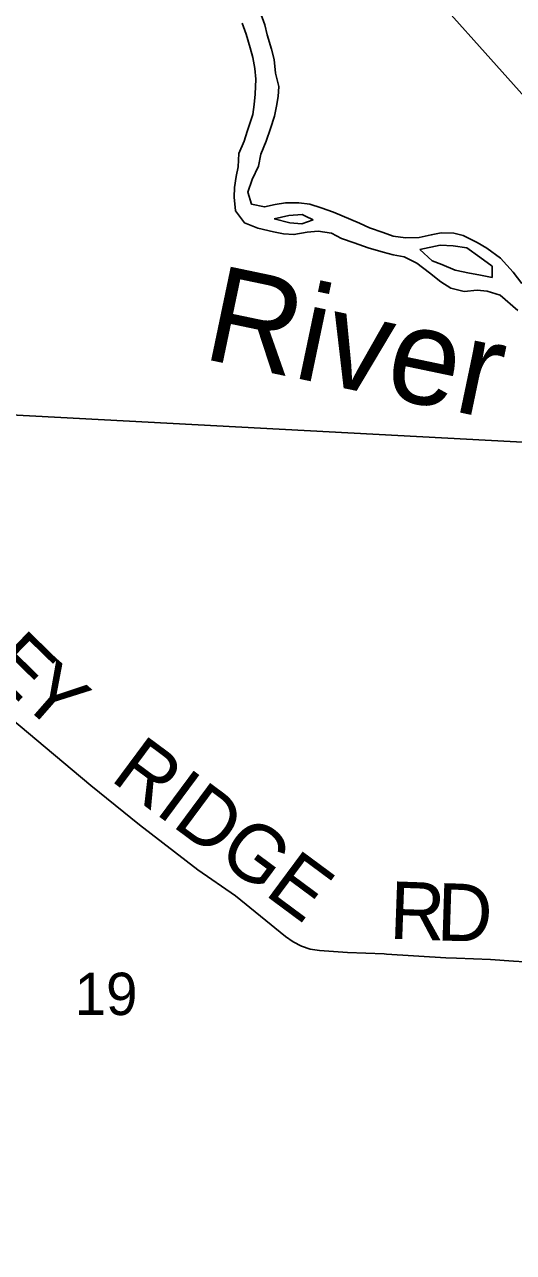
# Model space of a CAD drawing. Extents: x 39.8 to 73.8, y 13 to 35.
# Drawn here: x 45.577 to 46.061, y 28.175 to 29.389 of the extents above; entities that cross this region are included whole.
import ezdxf

# ---------------------------------------------------------------- set-up
doc = ezdxf.new("R2010")
doc.units = 0
for name, color, linetype in [('GM_X_Corporation', 7, 'Continuous'), ('GM_X_Major_River', 7, 'Continuous'), ('GM_X_Major_River_Text', 7, 'Continuous'), ('GM_X_Rail_Line', 7, 'Continuous'), ('GM_X_Section_Text', 7, 'Continuous'), ('GM_X_Township_Road', 7, 'Continuous'), ('GM_X_Township_Road_Text', 7, 'Continuous')]:
    doc.layers.add(name, color=color, linetype=linetype)

msp = doc.modelspace()

# ---------------------------------------------------------------- linework, layer by layer
at = {"layer": 'GM_X_Corporation'}
for points in [[(45.3612, 30.049), (46.3565, 29.9898), (46.2858, 28.9647), (45.2916, 29.0179)], [(45.2916, 29.0179), (46.2858, 28.9647), (46.2452, 27.9368), (45.2324, 28.0059)]]:
    msp.add_lwpolyline(points, close=True, dxfattribs=at)
at = {"layer": 'GM_X_Major_River'}
for p, q in [((45.8148, 29.389), (45.8097, 29.4026)), ((45.7924, 29.3907), (45.7963, 29.3798)), ((45.8171, 29.3792), (45.8148, 29.389)), ((45.7963, 29.3798), (45.8002, 29.3665)), ((45.8214, 29.3652), (45.8171, 29.3792)), ((45.8002, 29.3665), (45.8029, 29.3567)), ((45.8238, 29.355), (45.8214, 29.3652)), ((45.8029, 29.3567), (45.8049, 29.3461)), ((45.8254, 29.3414), (45.8238, 29.355)), ((45.8049, 29.3461), (45.8058, 29.3355)), ((45.8058, 29.3355), (45.8051, 29.3207)), ((45.8285, 29.3281), (45.8254, 29.3414)), ((45.8279, 29.3183), (45.8285, 29.3281)), ((45.8051, 29.3207), (45.8041, 29.3105)), ((45.8264, 29.3088), (45.8279, 29.3183)), ((45.8027, 29.3006), (45.7971, 29.2835)), ((45.8041, 29.3105), (45.8027, 29.3006)), ((45.8202, 29.2867), (45.8242, 29.2989)), ((45.8242, 29.2989), (45.8264, 29.3088)), ((45.8161, 29.2742), (45.8202, 29.2867)), ((45.7971, 29.2835), (45.7942, 29.274)), ((45.7942, 29.274), (45.789, 29.2618)), ((45.8109, 29.2613), (45.8161, 29.2742)), ((45.789, 29.2618), (45.7884, 29.2486)), ((45.8084, 29.2495), (45.8109, 29.2613)), ((45.7865, 29.2391), (45.7848, 29.2281)), ((45.7884, 29.2486), (45.7865, 29.2391)), ((45.8021, 29.2362), (45.8084, 29.2495)), ((45.7848, 29.2281), (45.7845, 29.2186)), ((45.798, 29.2236), (45.8021, 29.2362)), ((45.7845, 29.2186), (45.7857, 29.2053)), ((45.8015, 29.2119), (45.798, 29.2236)), ((45.7857, 29.2053), (45.7945, 29.1933)), ((45.8144, 29.209), (45.8015, 29.2119)), ((45.825, 29.2114), (45.8144, 29.209)), ((45.8352, 29.213), (45.825, 29.2114)), ((45.8484, 29.2131), (45.8352, 29.213)), ((45.8591, 29.2117), (45.8484, 29.2131)), ((45.8704, 29.208), (45.8591, 29.2117)), ((45.8826, 29.2039), (45.8704, 29.208)), ((45.9084, 29.1928), (45.8826, 29.2039)), ((45.7945, 29.1933), (45.8078, 29.1881)), ((45.8383, 29.2005), (45.8241, 29.1971)), ((45.8241, 29.1971), (45.8395, 29.1933)), ((45.8516, 29.2014), (45.8383, 29.2005)), ((45.8395, 29.1933), (45.8513, 29.1923)), ((45.8513, 29.1923), (45.8626, 29.1962)), ((45.8548, 29.1999), (45.8516, 29.2014)), ((45.8626, 29.1962), (45.8548, 29.1999)), ((45.9183, 29.1884), (45.9084, 29.1928)), ((45.8078, 29.1881), (45.8233, 29.1845)), ((45.8233, 29.1845), (45.8332, 29.1823)), ((45.8332, 29.1823), (45.8434, 29.1816)), ((45.8434, 29.1816), (45.8566, 29.184)), ((45.8566, 29.184), (45.8676, 29.1849)), ((45.8676, 29.1849), (45.8805, 29.1831)), ((45.8805, 29.1831), (45.8904, 29.1779)), ((45.8904, 29.1779), (45.9029, 29.1734)), ((45.9319, 29.1836), (45.9183, 29.1884)), ((45.9418, 29.1802), (45.9319, 29.1836)), ((45.9539, 29.1784), (45.9418, 29.1802)), ((45.9672, 29.1789), (45.9539, 29.1784)), ((45.9793, 29.1813), (45.9672, 29.1789)), ((45.9891, 29.1833), (45.9793, 29.1813)), ((46.0016, 29.183), (45.9891, 29.1833)), ((46.011, 29.1809), (46.0016, 29.183)), ((46.0247, 29.1738), (46.011, 29.1809)), ((45.9029, 29.1734), (45.9169, 29.1686)), ((45.9169, 29.1686), (45.9317, 29.1642)), ((45.988, 29.1712), (45.968, 29.1668)), ((45.968, 29.1668), (45.9802, 29.1556)), ((46.0009, 29.1705), (45.988, 29.1712)), ((46.0146, 29.1684), (46.0009, 29.1705)), ((46.0275, 29.1594), (46.0146, 29.1684)), ((46.0342, 29.1682), (46.0247, 29.1738)), ((46.0479, 29.1585), (46.0342, 29.1682)), ((45.9317, 29.1642), (45.9416, 29.1617)), ((45.9416, 29.1617), (45.9526, 29.1595)), ((45.9526, 29.1595), (45.9651, 29.1535)), ((45.9651, 29.1535), (45.9777, 29.1438)), ((45.9802, 29.1556), (45.9897, 29.1522)), ((46.0397, 29.1504), (46.0275, 29.1594)), ((46.0602, 29.1445), (46.0479, 29.1585)), ((45.9777, 29.1438), (45.9887, 29.1348)), ((45.9897, 29.1522), (46.003, 29.1463)), ((46.003, 29.1463), (46.017, 29.1434)), ((46.017, 29.1434), (46.0265, 29.142)), ((46.0265, 29.142), (46.0394, 29.1391)), ((46.0394, 29.1391), (46.0396, 29.1462)), ((46.0396, 29.1462), (46.0397, 29.1504)), ((46.069, 29.1333), (46.0602, 29.1445)), ((45.9887, 29.1348), (45.9986, 29.1288)), ((45.9986, 29.1288), (46.0119, 29.1255)), ((46.0119, 29.1255), (46.0248, 29.1268)), ((46.0248, 29.1268), (46.0346, 29.1257)), ((46.0346, 29.1257), (46.0475, 29.1217)), ((46.0475, 29.1217), (46.065, 29.1067))]:
    msp.add_line(p, q, dxfattribs=at)
for points in [[(45.8097, 29.4026), (45.8148, 29.389), (45.8171, 29.3792), (45.8214, 29.3652), (45.8238, 29.355), (45.8254, 29.3414), (45.8285, 29.3281), (45.8279, 29.3183), (45.8264, 29.3088), (45.8242, 29.2989), (45.8202, 29.2867), (45.8161, 29.2742), (45.8109, 29.2613), (45.8084, 29.2495), (45.8021, 29.2362), (45.798, 29.2236), (45.8015, 29.2119), (45.8144, 29.209), (45.825, 29.2114), (45.8352, 29.213), (45.8484, 29.2131), (45.8591, 29.2117), (45.8704, 29.208), (45.8826, 29.2039), (45.9084, 29.1928), (45.9183, 29.1884), (45.9319, 29.1836), (45.9418, 29.1802), (45.9539, 29.1784), (45.9672, 29.1789), (45.9793, 29.1813), (45.9891, 29.1833), (46.0016, 29.183), (46.011, 29.1809), (46.0247, 29.1738), (46.0342, 29.1682), (46.0479, 29.1585), (46.0602, 29.1445), (46.069, 29.1333)], [(45.7924, 29.3907), (45.7963, 29.3798), (45.8002, 29.3665), (45.8029, 29.3567), (45.8049, 29.3461), (45.8058, 29.3355), (45.8051, 29.3207), (45.8041, 29.3105), (45.8027, 29.3006), (45.7971, 29.2835), (45.7942, 29.274), (45.789, 29.2618), (45.7884, 29.2486), (45.7865, 29.2391), (45.7848, 29.2281), (45.7845, 29.2186), (45.7857, 29.2053), (45.7945, 29.1933), (45.8078, 29.1881), (45.8233, 29.1845), (45.8332, 29.1823), (45.8434, 29.1816), (45.8566, 29.184), (45.8676, 29.1849), (45.8805, 29.1831), (45.8904, 29.1779), (45.9029, 29.1734), (45.9169, 29.1686), (45.9317, 29.1642), (45.9416, 29.1617), (45.9526, 29.1595), (45.9651, 29.1535), (45.9777, 29.1438), (45.9887, 29.1348), (45.9986, 29.1288), (46.0119, 29.1255), (46.0248, 29.1268), (46.0346, 29.1257), (46.0475, 29.1217), (46.065, 29.1067)]]:
    msp.add_lwpolyline(points, dxfattribs=at)
at = {"layer": 'GM_X_Rail_Line'}
msp.add_lwpolyline([(45.9623, 29.4402), (46.0662, 29.3238), (46.1347, 29.2466), (46.2135, 29.1583), (46.2865, 29.0768), (46.3418, 29.0147), (46.3979, 28.9519), (46.509, 28.8273), (46.5395, 28.7929), (46.5551, 28.774), (46.5729, 28.7504), (46.5851, 28.7317), (46.5997, 28.7075), (46.6102, 28.687), (46.6194, 28.6688), (46.627, 28.6512), (46.6389, 28.6202), (46.6503, 28.5861), (46.6665, 28.5365), (46.6927, 28.4558), (46.7997, 28.1307)], dxfattribs=at)
at = {"layer": 'GM_X_Township_Road'}
for points in [[(45.5644, 28.7022), (45.5974, 28.6746), (45.6425, 28.6367), (45.6907, 28.5977), (45.7484, 28.5533), (45.7857, 28.5276), (45.835, 28.4874), (45.8426, 28.482), (45.8509, 28.4778), (45.8597, 28.4749), (45.8689, 28.4734), (45.8965, 28.4716), (45.9329, 28.47), (45.9349, 28.4699)], [(45.9349, 28.4699), (45.9938, 28.4661), (46.0044, 28.466), (46.038, 28.4645), (46.0606, 28.4629), (46.0717, 28.4622)]]:
    msp.add_lwpolyline(points, dxfattribs=at)

# ---------------------------------------------------------------- texts
at = {"layer": 'GM_X_Major_River_Text'}
msp.add_text('River', height=0.09469, rotation=348.1697, dxfattribs=at).set_placement((45.7514, 29.0593))
at = {"layer": 'GM_X_Section_Text'}
msp.add_text('19', height=0.04186, rotation=0, dxfattribs=at).set_placement((45.6265, 28.4096))
at = {"layer": 'GM_X_Township_Road_Text'}
for s, height, rotation, p in [('E', 0.0568, 315.7128, (45.5371, 28.7528)), ('Y', 0.0568, 318.7749, (45.57, 28.7208)), ('RIDGE', 0.05682, 323.4446, (45.6607, 28.6425)), ('R', 0.0568, 357.9348, (45.9373, 28.4852)), ('D', 0.0568, 358.1608, (45.9842, 28.4835))]:
    msp.add_text(s, height=height, rotation=rotation, dxfattribs=at).set_placement(p)

doc.saveas('drawing.dxf')
